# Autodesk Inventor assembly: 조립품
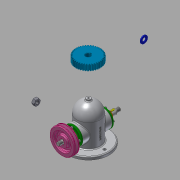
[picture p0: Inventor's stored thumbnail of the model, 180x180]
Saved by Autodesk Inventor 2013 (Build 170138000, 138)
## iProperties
Created: 2019-11
Part Number: 조립품
Document SubType Name: Assembly
Designer: Administrator
Author: Administrator
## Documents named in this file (14)
- C:\Users\Administrator\Desktop\491104V1038\조립품.iam
- C:\Users\Administrator\Desktop\491104V1038\본체.ipt
- C:\Users\Administrator\Desktop\491104V1038\V-벨트풀리.ipt
- V-벨트풀리.ipt
- C:\Users\Administrator\Desktop\491104V1038\너트 M12x1.25.ipt
- C:\Users\Administrator\Desktop\491104V1038\베어링 6203.ipt
- C:\Users\Administrator\Desktop\491104V1038\볼트 M4.ipt
- C:\Users\Administrator\Desktop\491104V1038\부시.ipt
- C:\Users\Administrator\Desktop\491104V1038\스퍼기어.ipt
- C:\Users\Administrator\Desktop\491104V1038\오일 실 26 38 8.ipt
- C:\Users\Administrator\Desktop\491104V1038\와셔 12x24.ipt
- C:\Users\Administrator\Desktop\491104V1038\축.ipt
- C:\Users\Administrator\Desktop\491104V1038\커버.ipt
- C:\Users\Administrator\Desktop\491104V1038\키 5x5x12.ipt
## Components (1 placed, 1 different names)
1. V-벨트풀리:1
